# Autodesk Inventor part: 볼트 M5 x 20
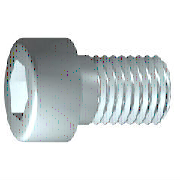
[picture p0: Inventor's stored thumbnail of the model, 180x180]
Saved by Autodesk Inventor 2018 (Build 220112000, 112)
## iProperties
Created: 2012-02
Part Number: 볼트 M5 x 20
Material: 스테인리스강
Description: 6각 소켓 머리 캡 나사
Document SubType Name: Modeling
Standard: ISO 4762
Designer: mduedu
Standard Revision: Fourth edition 2004-03-01
Standards Organization: ISO
Language: ko-KR
Size Designation: M5 x 20
Categories: <MemberInstance><Categories><Category DisplayName="조임쇠" InternalName="e4da775c-781d-43d5-af7c-5136215cf5a6" Mnemonic="FSTN"><Category DisplayName="볼트" InternalN
Density: 8.08 g/cm^3
Mass: 5.10181 g
Surface Area: 5.88237 cm^2
Volume: 0.631412 cm^3
Appearance: 반광택
IsCustomPart: 0
Author: mduedu
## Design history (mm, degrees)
sketch "스케치1"
  geometry: L1 (-1.167, 0)-(20, 0); L2 (20, 0)-(20, 2.5); L3 (20, 2.5)-(2, 2.5); L4 (2, 2.5)-(1.509, 2.5); L5 (1.509, 2.5)-(0, 2.5); L6 (0, 2.5)-(0, 4.25); L7 (0, 4.25)-(-5, 4.25); L8 (-5, 4.25)-(-5, 2.309); L9 (-5, 2.309)-(-2.5, 2.309); L10 (-2.5, 2.309)-(-1.167, 0); L11 (-10, 0)-(25, 0) reference; L12 (0, -0.85)-(0, 5.1) reference; L13 (2, 2.5)-(0, 2.5)
  constraints: 22 end point, 6 parallel, 2 collinear, 2 perpendicular, 1 horizontal, 1 point on line
  dimensions: "d1" = 18 distance from line of L3.end L2 (= GEL); "d2" = 0.49086 distance of L4.end L3.end (computed from GAL); "d3" = 5 distance between parallel lines of L8 L6 (= KOH); "d4" = 2.5 distance of L8.end L9.end (= INTI); "d5" = 60 deg angle of L10 L1; "d6" = 5 diameter of L3 L1 (= GD); "d7" = 5 diameter of L5 L1 (= BDM); "d8" = 4.6188 diameter of L9 L1 (= 1.1547 x SW); "d9" = 8.5 diameter of L7 L1 (= KOD); "d26" = 20 distance between parallel lines of L12 L2 (= NLG)
revolve "본체" sketch "스케치1" stored, may be unused: angle "d10" = 90 deg
sketch "스케치2"
  geometry: L1 (0, -5.95)-(0, 5.95) reference; L2 (-5.95, 0)-(5.95, 0) reference; L3 (2.309, 0)-(1.155, -2); L4 (1.155, -2)-(-1.155, -2); L5 (-1.155, -2)-(-2.309, 0); L6 (-2.309, 0)-(-1.155, 2); L7 (-1.155, 2)-(1.155, 2); L8 (1.155, 2)-(2.309, 0); 2 further points
  constraints: 12 end point, 1 coincident, 1 horizontal alignment, 1 point on line, 12 other
extrude "슬롯" join sketch "스케치2" stored distance "d11" = 10; taper "d12" = 0 deg
workplane "Work Plane1"
fillet "Fillet2" dims "d30" = 0.1 (= R)
body "Solid1"
fillet "모깎기1" dims "d17" = 0.5 (= RR)
feature "스레드" dims "d13" = 18 (= GEL), "d14" = 0
chamfer "모따기1" distance "d15" = 0.49076 (= -0.5 x SPD + 0.5 x GD); stored, may be unused: second distance "d16" = 0.49076 (= GUL), angle "d27" = 45 deg
other parameters: "GD" = 5 [user parameter; used in 2 equation terms], "NLG" = 20 [user parameter; used in 1 equation term], "GEL" = 18 [user parameter; used in 2 equation terms], "KOD" = 8.5 [user parameter; used in 1 equation term], "KOH" = 5 [user parameter; used in 1 equation term], "INTI" = 2.5 [user parameter; used in 1 equation term], "GAL" = 0.49076 (= 0.61345 x PTC) [user parameter; used in 1 equation term], "GUL" = 0.49076 (= 0.61345 x PTC) [user parameter; used in 1 equation term], "BDM" = 5 (= NND) [user parameter; used in 1 equation term], "SW" = 4 [user parameter; used in 2 equation terms], "RR" = 0.5 [user parameter; used in 1 equation term], "SPD" = 4.01848 (= NND - 1.2269 x PTC) [user parameter; used in 1 equation term], "d19" = 0, "d28" = 0, "d29" = 0, "R" = 0.1 [user parameter; used in 1 equation term], "TOA" = 30 deg [user parameter], "GD1" = 4.01848 (= THREADDIA - 1.2269 x PTC) [user parameter], "THREADDIA" = 5 [user parameter; used in 1 equation term], "FAWI" = 45 deg [user parameter], "TPU" = 12.5 (computed from PTC) [user parameter], "PTC" = 0.8 [user parameter; used in 5 equation terms], "NND" = 5 [user parameter; used in 2 equation terms], "E0" = 4.62 (= 1.155 x SW) [user parameter]
